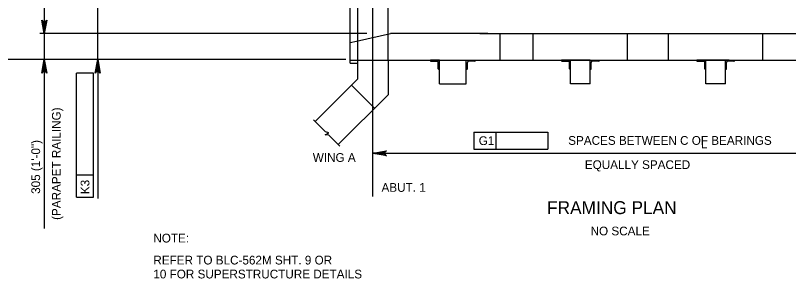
# Model space of a CAD drawing. Extents: x 638263 to 640360, y 293683 to 298655.
# Drawn here: x 638498.8 to 638763.9, y 294608.3 to 294698.5 of the extents above; entities that cross this region are included whole.
import ezdxf

# ---------------------------------------------------------------- set-up
doc = ezdxf.new("R2010")
doc.units = 0
for name, color, linetype in [('2', 7, 'Continuous'), ('3', 7, 'Continuous'), ('4', 7, 'Continuous')]:
    doc.layers.add(name, color=color, linetype=linetype)

msp = doc.modelspace()

# ---------------------------------------------------------------- linework, layer by layer
at = {"layer": '2'}
for p, q in [((638613.6, 294682.15), (638613.6, 294790.36)), ((638616.27, 294683.1), (638616.27, 294789.4)), ((638626.57, 294683.1), (638626.57, 294789.4)), ((638615.77, 294689.62), (638627.45, 294692.22)), ((638660.75, 294692.22), (638627.45, 294692.22)), ((638658.08, 294692.22), (638802.82, 294692.22)), ((638664.97, 294683.1), (638664.97, 294692.22)), ((638676.37, 294683.1), (638676.37, 294692.22)), ((638708.71, 294683.1), (638708.71, 294692.22)), ((638722.74, 294683.1), (638722.74, 294692.22)), ((638755.08, 294683.1), (638755.08, 294692.22)), ((638613.6, 294689.13), (638615.77, 294689.62)), ((638613.6, 294683.1), (638816.67, 294683.1)), ((638613.6, 294682.15), (638616.27, 294682.15)), ((638616.27, 294676.71), (638616.27, 294683.1)), ((638626.57, 294683.1), (638626.57, 294671.26)), ((638641.1, 294682.92), (638641.1, 294683.1)), ((638644.19, 294683.1), (638641.1, 294683.1)), ((638641.28, 294682.74), (638643.46, 294682.74)), ((638643.82, 294680.19), (638643.82, 294682.38)), ((638644.19, 294683.1), (638653.42, 294683.1)), ((638644.19, 294680.01), (638644.19, 294683.1)), ((638644.19, 294675.01), (638644.19, 294683.1)), ((638653.42, 294680.01), (638653.42, 294683.1)), ((638653.42, 294683.1), (638656.51, 294683.1)), ((638653.42, 294675.01), (638653.42, 294683.1)), ((638653.79, 294680.19), (638653.79, 294682.38)), ((638656.33, 294682.74), (638654.15, 294682.74)), ((638656.51, 294682.92), (638656.51, 294683.1)), ((638686.09, 294682.92), (638686.09, 294683.1)), ((638689.18, 294683.1), (638686.09, 294683.1)), ((638686.27, 294682.74), (638688.45, 294682.74)), ((638688.82, 294680.19), (638688.82, 294682.38)), ((638689.18, 294680.01), (638689.18, 294683.1)), ((638695.91, 294683.1), (638689.18, 294683.1)), ((638689.18, 294675.01), (638689.18, 294683.1)), ((638695.91, 294680.01), (638695.91, 294683.1)), ((638695.91, 294683.1), (638699, 294683.1)), ((638695.91, 294675.01), (638695.91, 294683.1)), ((638696.27, 294680.19), (638696.27, 294682.38)), ((638698.82, 294682.74), (638696.64, 294682.74)), ((638699, 294682.92), (638699, 294683.1)), ((638732.45, 294682.92), (638732.45, 294683.1)), ((638735.54, 294683.1), (638732.45, 294683.1)), ((638732.64, 294682.74), (638734.82, 294682.74)), ((638743.53, 294683.1), (638734.29, 294683.1)), ((638735.18, 294680.19), (638735.18, 294682.38)), ((638742.27, 294683.1), (638735.54, 294683.1)), ((638735.54, 294680.01), (638735.54, 294683.1)), ((638735.54, 294675.01), (638735.54, 294683.1)), ((638742.27, 294680.01), (638742.27, 294683.1)), ((638742.27, 294683.1), (638745.36, 294683.1)), ((638742.27, 294675.01), (638742.27, 294683.1)), ((638742.63, 294680.19), (638742.63, 294682.38)), ((638745.18, 294682.74), (638743, 294682.74)), ((638745.36, 294682.92), (638745.36, 294683.1)), ((638644, 294680.01), (638644.19, 294680.01)), ((638653.6, 294680.01), (638653.42, 294680.01)), ((638689, 294680.01), (638689.18, 294680.01)), ((638696.09, 294680.01), (638695.91, 294680.01)), ((638735.36, 294680.01), (638735.54, 294680.01)), ((638742.45, 294680.01), (638742.27, 294680.01)), ((638616.27, 294676.71), (638601.61, 294662.05)), ((638616.27, 294676.71), (638614.07, 294674.51)), ((638614.07, 294674.51), (638621.94, 294666.63)), ((638644.19, 294675.01), (638653.42, 294675.01)), ((638695.91, 294675.01), (638689.18, 294675.01)), ((638742.27, 294675.01), (638735.54, 294675.01)), ((638742.27, 294675.01), (638735.54, 294675.01)), ((638626.57, 294671.26), (638609.48, 294654.18))]:
    msp.add_line(p, q, dxfattribs=at)
for centre, radius, start, end in [((638641.28, 294682.92), 0.182, 180.0016, 270), ((638643.46, 294682.38), 0.364, 0.0016, 90), ((638654.15, 294682.38), 0.364, 90, 179.9984), ((638656.33, 294682.92), 0.182, 270, 359.9984), ((638686.27, 294682.92), 0.182, 180.0016, 270), ((638688.45, 294682.38), 0.364, 0.0016, 90), ((638696.64, 294682.38), 0.364, 90, 179.9984), ((638698.82, 294682.92), 0.182, 270, 359.9984), ((638732.64, 294682.92), 0.182, 180.0016, 270), ((638734.82, 294682.38), 0.364, 0.0016, 90), ((638743, 294682.38), 0.364, 90, 179.9984), ((638745.18, 294682.92), 0.182, 270, 359.9984), ((638644, 294680.19), 0.182, 180.0016, 270), ((638653.6, 294680.19), 0.182, 270, 359.9984), ((638689, 294680.19), 0.182, 180.0016, 270), ((638696.09, 294680.19), 0.182, 270, 359.9984), ((638735.36, 294680.19), 0.182, 180.0016, 270), ((638742.45, 294680.19), 0.182, 270, 359.9984)]:
    msp.add_arc(centre, radius, start, end, dxfattribs=at)
at = {"layer": '3'}
for p, q in [((638621.42, 294636.37), (638621.42, 294839.45)), ((638601.01, 294662.66), (638605.09, 294658.58)), ((638606.34, 294658.18), (638605.09, 294658.58)), ((638605.01, 294657.52), (638606.34, 294658.18)), ((638606.3, 294657.36), (638605.01, 294657.52)), ((638606.3, 294657.36), (638610.04, 294653.63))]:
    msp.add_line(p, q, dxfattribs=at)
at = {"layer": '4'}
for p, q in [((638508.72, 294845.63), (638508.72, 294625.42)), ((638527.05, 294683.37), (638527.05, 294789.67)), ((638619.32, 294692.22), (638507.24, 294692.22)), ((638612.16, 294683.37), (638493.53, 294683.37)), ((638527.05, 294680.54), (638527.05, 294677.7)), ((638525.64, 294678.68), (638519.74, 294678.69)), ((638519.74, 294643.73), (638519.74, 294678.69)), ((638525.64, 294636.16), (638525.64, 294678.68)), ((638527.05, 294677.7), (638527.05, 294635.75)), ((638656.01, 294658.49), (638663.57, 294658.49)), ((638656.01, 294658.49), (638656.01, 294652.58)), ((638663.57, 294658.49), (638663.57, 294652.58)), ((638663.57, 294658.49), (638681.32, 294658.49)), ((638681.32, 294658.49), (638681.32, 294652.58)), ((638621.42, 294651.22), (638809, 294651.22)), ((638656.01, 294652.58), (638681.32, 294652.58)), ((638519.74, 294636.17), (638519.74, 294643.73)), ((638525.64, 294643.72), (638519.74, 294643.73)), ((638519.74, 294636.17), (638525.64, 294636.16))]:
    msp.add_line(p, q, dxfattribs=at)
for points in [[(638508.72, 294692.22), (638507.85, 294696.89), (638508.1, 294696.53), (638508.41, 294696.34), (638508.72, 294696.29), (638509.03, 294696.34), (638509.35, 294696.53), (638509.59, 294696.89), (638508.72, 294692.22), (638509.35, 294696.53), (638509.03, 294696.34), (638508.72, 294692.22), (638508.72, 294696.29), (638508.41, 294696.34), (638508.72, 294692.22), (638508.1, 294696.53)], [(638508.72, 294683.37), (638509.59, 294678.71), (638509.35, 294679.07), (638509.03, 294679.26), (638508.72, 294679.31), (638508.41, 294679.26), (638508.1, 294679.07), (638507.85, 294678.71), (638508.72, 294683.37), (638508.1, 294679.07), (638508.41, 294679.26), (638508.72, 294683.37), (638508.72, 294679.31), (638509.03, 294679.26), (638508.72, 294683.37), (638509.35, 294679.07)], [(638527.05, 294683.37), (638527.92, 294678.71), (638527.68, 294679.07), (638527.36, 294679.26), (638527.05, 294679.31), (638526.74, 294679.26), (638526.43, 294679.07), (638526.18, 294678.71), (638527.05, 294683.37), (638526.43, 294679.07), (638526.74, 294679.26), (638527.05, 294683.37), (638527.05, 294679.31), (638527.36, 294679.26), (638527.05, 294683.37), (638527.68, 294679.07)], [(638621.42, 294651.22), (638626.08, 294652.09), (638625.72, 294651.85), (638625.54, 294651.53), (638625.48, 294651.22), (638625.54, 294650.91), (638625.72, 294650.6), (638626.08, 294650.35), (638621.42, 294651.22), (638625.72, 294650.6), (638625.54, 294650.91), (638621.42, 294651.22), (638625.48, 294651.22), (638625.54, 294651.53), (638621.42, 294651.22), (638625.72, 294651.85)]]:
    msp.add_lwpolyline(points, dxfattribs=at)

# ---------------------------------------------------------------- texts
for s, rotation, p in [('(PARAPET RAILING)', 90, (638514.36, 294628.36)), ('G1', 359.9382, (638657.67, 294654.03)), ('305 (1\'-0")', 90, (638507.29, 294637.29)), ('K3', 89.9382, (638524.19, 294637.19))]:
    msp.add_text(s, height=3, rotation=rotation, dxfattribs=at).set_placement(p)
for s, height, p in [('SPACES BETWEEN C OF BEARINGS', 3, (638688.36, 294654.1)), ('L', 3, (638733.85, 294652.93)), ('WING A', 3, (638600.78, 294648.26)), ('EQUALLY SPACED', 3, (638694.06, 294645.8)), ('ABUT. 1', 3, (638624.35, 294637.99)), ('FRAMING PLAN', 4.4292, (638681.1, 294630.35)), ('NO SCALE', 3, (638696.03, 294623.06)), ('NOTE:', 3, (638546.12, 294620.62)), ('REFER TO BLC-562M SHT. 9 OR', 3, (638546.12, 294613.08)), ('10 FOR SUPERSTRUCTURE DETAILS', 3, (638546.12, 294608.3))]:
    msp.add_text(s, height=height, dxfattribs=at).set_placement(p)

doc.saveas('drawing.dxf')
